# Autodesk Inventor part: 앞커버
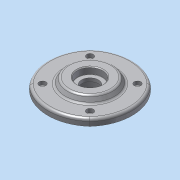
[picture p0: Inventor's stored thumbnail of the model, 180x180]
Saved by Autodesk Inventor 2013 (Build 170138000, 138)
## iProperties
Company: 한국ATC센터
Created: 2014-08
Part Number: 앞커버
Document SubType Name: Modeling
Designer: KYOUNG IL JANG
Density: 2.71 g/cm^3
Material: 알루미늄 6061
Mass: 241.248 g
Surface Area: 231.959 cm^2
Volume: 89.0213 cm^3
Author: KYOUNG IL JANG
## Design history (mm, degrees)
sketch "스케치1"
  geometry: C1 r 30 at (0, 0) reference; A1 r 53.623 centre (0, -3.623) between (36.062, 36.062) and (-36.062, 36.062) reference; A2 r 53.623 centre (3.623, 0) between (-36.062, 36.062) and (-36.062, -36.062) reference; A3 r 53.623 centre (-3.623, 0) between (36.062, -36.062) and (36.062, 36.062) reference; A4 r 53.623 centre (0, 3.623) between (-36.062, -36.062) and (36.062, -36.062) reference; 1 further point
  node "참조9"
  node "참조14"
  node "참조15"
  node "참조16"
  node "참조17"
extrude "돌출1" new body sketch "스케치1" distance "d0" = 8; taper "d1" = 0 deg
sketch "스케치2"
  geometry: C1 r 30 at (0, 0); 1 further point
  constraints: 1 centre point, 1 coincident
  dimensions: "d2" = 60 diameter of C1
extrude "돌출2" join sketch "스케치2" distance "d3" = 7; taper "d4" = -30 deg
hole "구멍1" diameter "d7" = 20; stored, may be unused: countersink angle "d11" = 90 deg, drill point angle "d13" = 118 deg; dims "d5" = 10, "d6" = 10, "d8" = 6, "d9" = 30, "d10" = 8, "d12" = 20
sketch "스케치3"
  geometry: C1 r 1.621 at (28.284, 28.284) reference; C2 r 1.621 at (-28.284, 28.284) reference; C3 r 1.621 at (-28.284, -28.284) reference; C4 r 1.621 at (28.284, -28.284) reference; 1 further point
hole "구멍2" sketch "스케치3" at (28.284, 28.284), (28.284, -28.284), (-28.284, -28.284), (-28.284, 28.284) diameter "d14" = 4.5; stored, may be unused: countersink angle "d18" = 90 deg, drill point angle "d20" = 118 deg; dims "d15" = 6, "d16" = 8, "d17" = 4.4, "d19" = 20
extrude "돌출3" join sketch "스케치1" distance "d21" = 12; taper "d22" = 0 deg
hole "구멍3" diameter "d25" = 30; stored, may be unused: countersink angle "d29" = 90 deg, drill point angle "d31" = 0 deg; dims "d23" = 10, "d24" = 10, "d26" = 6, "d27" = 40, "d28" = 12, "d30" = 15
fillet "모깎기1" dims "d32" = 3, "d33" = 0.3
chamfer "모따기1" distance "d34" = 1; stored, may be unused: second distance "d35" = 2, angle "d36" = 45 deg
node "솔리드1"
node "참조10"
node "참조11"
node "참조12"
node "참조13"
